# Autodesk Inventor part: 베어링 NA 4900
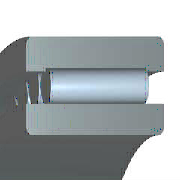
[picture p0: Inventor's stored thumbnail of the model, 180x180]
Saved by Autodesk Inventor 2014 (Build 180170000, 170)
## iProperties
Created: 2009-02
Part Number: 베어링 NA 4900
Material: Steel, Mild
Description: 니들 롤러 베어링 - 경계 치수 및 공차
Document SubType Name: Modeling
Standard: KS B 2029
Designer: KYOUNG IL JANG
Standards Organization: KS
Language: ko-KR
Size Designation: NA 4900 - 10 x 22 x 13
Categories: <MemberInstance><Categories><Category DisplayName="샤프트 부품" InternalName="7f7aeb1f-a693-4053-b835-cee3144e0d98" Mnemonic="SHFT"><Category DisplayName="베어링" Inter
Density: 7.86 g/cm^3
Mass: 23.8213 g
Surface Area: 38.613 cm^2
Volume: 3.0307 cm^3
Appearance: Metal-Steel
Company: 한국ATC센터
IsCustomPart: 0
Author: KYOUNG IL JANG
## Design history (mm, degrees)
sketch "스케치"
  geometry: L1 (1.857, 9)-(11.143, 9); L2 (11.143, 9)-(11.143, 7); L3 (13, 7)-(0, 7); L4 (1.857, 7)-(1.857, 9); L5 (1.857, 8)-(11.143, 8); L6 (6.5, 8)-(6.5, 7); L7 (0, 5)-(13, 5); L8 (0, 11)-(13, 11); L9 (13, 5)-(13, 7); L10 (13, 8.8)-(13, 11); L11 (1.857, 8.8)-(0, 8.8); L12 (11.143, 8.8)-(13, 8.8); L13 (-6, 0)-(36, 0) reference; L14 (0, -1.9)-(0, 14.9) reference
  constraints: 24 end point, 8 point on line, 3 midpoint, 3 parallel, 3 perpendicular, 2 symmetric about line, 1 horizontal, 1 other
  dimensions: "d6" = 10 diameter of L7 L13 (= WD); "d7" = 14 diameter of L3 L13 (= KID1); "d8" = 22 diameter of L8 L13 (= BD); "d9" = 16 diameter of L6.start L13 (= 0.5 x WD + 0.5 x BD); "d10" = 17.6 diameter of L12 L13 (= 0.9 x BD + 0.9 x WD - 0.8 x KID1); "d11" = 18 diameter of L1 L13 (= BD + WD - KID1); "d12" = 1.85714 distance between parallel lines of L14 L4 (= 0.142857 x KB); "d13" = 13 distance between parallel lines of L14 L9 (= KB); "d14" = 11.14286 distance between parallel lines of L14 L2 (= 0.857143 x KB)
revolve "본체" stored, may be unused: angle "d17" = 90 deg
revolve "롤러" stored, may be unused: angle "d18" = 90 deg
pattern_circular "IDS_ARRAYROLLER[SIMPL:T]" dims angle "d2" = 360 deg
body "Solid1"
fillet "모깎기1" dims "d0" = 0.3 (= KRS)
other parameters: "WD" = 10 [user parameter; used in 6 equation terms], "BD" = 22 [user parameter; used in 6 equation terms], "KB" = 13 [user parameter; used in 3 equation terms], "KID1" = 14 [user parameter; used in 4 equation terms], "KRS" = 0.3 [user parameter; used in 1 equation term], "d3" = 0, "d4" = 0, "d5" = 0, "d15" = 0, "d16" = 0, "BC0" = 9150000 [user parameter], "WR" = 5 (= 0.5 x WD) [user parameter], "BBA" = 0 [user parameter], "BC" = 8150000 [user parameter], "BR" = 11 (= 0.5 x BD) [user parameter]
